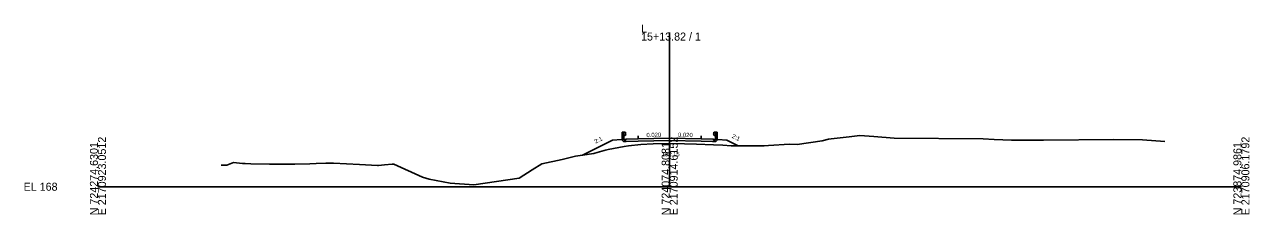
# Model space of a CAD drawing. Extents: x -26 to 2803, y -10 to 9553.
# Drawn here: x -25.7 to 402.8, y 6490.3 to 6556.7 of the extents above; entities that cross this region are included whole.
import ezdxf

# ---------------------------------------------------------------- set-up
doc = ezdxf.new("R2010")
doc.units = 0
for name, color, linetype in [('Exist Cross Section Cell', 7, 'Continuous'), ('Exist XS Center Line Elevation Label', 7, 'Continuous'), ('Exist XS Ground Line', 7, 'Continuous'), ('Prop XS Dump Level', 7, 'Continuous'), ('Prop XS Earthwork Shape', 7, 'Continuous'), ('Prop XS EOT Tick Mark', 7, 'Continuous'), ('Prop XS Finish Grade', 7, 'Continuous'), ('Prop XS Finish Grade Earthwork', 7, 'Continuous'), ('Prop XS Finish Grade Paved Shoulder', 7, 'Continuous'), ('Prop XS Finish Grade Pavement', 7, 'Continuous'), ('Prop XS Guardrail', 7, 'Continuous'), ('Prop XS Pvmt Edge Slope', 7, 'Continuous'), ('Prop XS SE Text', 7, 'Continuous'), ('Prop XS Side Slope Text', 7, 'Continuous'), ('Prop XS Subgrade Earthwork', 7, 'Continuous')]:
    doc.layers.add(name, color=color, linetype=linetype)

msp = doc.modelspace()

# ---------------------------------------------------------------- linework, layer by layer
at = {"layer": 'Exist Cross Section Cell'}
for p, q in [((200, 6500), (200, 6553.89)), ((0, 6500), (200, 6500)), ((200, 6500), (400, 6500))]:
    msp.add_line(p, q, dxfattribs=at)
at = {"layer": 'Exist XS Ground Line'}
msp.add_lwpolyline([(43.07, 6507.56), (45.03, 6507.5), (47.38, 6508.45), (50.61, 6508.11), (51.5, 6508.08), (53.51, 6508.04), (60.02, 6507.91), (61.85, 6507.9), (66.19, 6507.89), (68.85, 6507.89), (74.18, 6508.05), (76.36, 6508.11), (79.77, 6508.28), (82.39, 6508.2), (91.49, 6507.8), (97.75, 6507.46), (98.09, 6507.46), (100.29, 6507.71), (102.96, 6507.89), (103.52, 6507.94), (113.58, 6503.39), (115.83, 6502.7), (123.27, 6501.22), (131.48, 6500.69), (147.3, 6502.96), (151.91, 6505.9), (155.32, 6508.06), (162.41, 6509.53), (167.1, 6510.74), (173.51, 6511.58), (173.81, 6511.78), (177.09, 6512.67), (177.54, 6512.82), (178.45, 6513.01), (184.13, 6514.11), (185.65, 6514.27), (189.86, 6514.79), (194.25, 6514.97), (199.83, 6515.16), (205.22, 6514.98), (209.44, 6514.86), (215.28, 6514.67), (218.61, 6514.58), (221.57, 6514.34), (222.7, 6514.29), (225.56, 6514.29), (229.95, 6514.26), (233.04, 6514.31), (234.55, 6514.43), (241.9, 6514.83), (244.66, 6514.82), (253.38, 6516), (255.54, 6516.57), (256.48, 6516.69), (262.79, 6517.47), (266.53, 6517.96), (271.41, 6517.53), (278.54, 6516.97), (309.65, 6516.71), (313.52, 6516.54), (319.61, 6516.26), (320.03, 6516.26), (330.82, 6516.33), (355.34, 6516.51), (365.4, 6516.4), (373.27, 6515.84)], dxfattribs=at)
at = {"layer": 'Prop XS Dump Level'}
for p, q in [((189, 6516.76), (200, 6516.98)), ((200, 6516.98), (211, 6516.76))]:
    msp.add_line(p, q, dxfattribs=at)
at = {"layer": 'Prop XS Earthwork Shape'}
msp.add_lwpolyline([(211, 6515.92), (200, 6516.14), (189, 6515.92), (184.75, 6515.84), (183.9, 6515.82), (183.18, 6516.55), (180, 6516.29), (169.53, 6511.06), (173.51, 6511.58), (173.81, 6511.78), (177.09, 6512.67), (177.54, 6512.82), (178.45, 6513.01), (184.13, 6514.11), (185.65, 6514.27), (189.86, 6514.79), (194.25, 6514.97), (199.83, 6515.16), (205.22, 6514.98), (209.44, 6514.86), (215.28, 6514.67), (218.61, 6514.58), (221.57, 6514.34), (222.7, 6514.29), (224.01, 6514.29), (220, 6516.29), (216.82, 6516.55), (216.1, 6515.82), (215, 6515.84)], close=True, dxfattribs=at)
at = {"layer": 'Prop XS EOT Tick Mark'}
for p, q in [((189, 6516.76), (189, 6517.76)), ((211, 6516.76), (211, 6517.76))]:
    msp.add_line(p, q, dxfattribs=at)
at = {"layer": 'Prop XS Finish Grade'}
for p, q in [((184.75, 6516.67), (183.18, 6516.55)), ((215.25, 6516.67), (216.82, 6516.55))]:
    msp.add_line(p, q, dxfattribs=at)
at = {"layer": 'Prop XS Finish Grade Earthwork'}
for p, q in [((180, 6516.29), (169.53, 6511.06)), ((183.18, 6516.55), (180, 6516.29)), ((216.82, 6516.55), (220, 6516.29)), ((220, 6516.29), (224.01, 6514.29))]:
    msp.add_line(p, q, dxfattribs=at)
at = {"layer": 'Prop XS Finish Grade Paved Shoulder'}
for p, q in [((189, 6516.76), (184.75, 6516.67)), ((211, 6516.76), (215.25, 6516.67))]:
    msp.add_line(p, q, dxfattribs=at)
at = {"layer": 'Prop XS Finish Grade Pavement'}
for p, q in [((189, 6516.76), (200, 6516.98)), ((200, 6516.98), (211, 6516.76))]:
    msp.add_line(p, q, dxfattribs=at)
at = {"layer": 'Prop XS Guardrail'}
for p, q in [((183.43, 6519.06), (183.93, 6519.06)), ((183.43, 6516.56), (183.43, 6519.06)), ((183.93, 6519.06), (184.43, 6519.06)), ((183.93, 6519.06), (183.93, 6516.56)), ((184.43, 6519.06), (184.72, 6518.86)), ((184.72, 6518.74), (184.43, 6518.54)), ((184.43, 6518.54), (184.43, 6518.45)), ((184.43, 6518.45), (184.72, 6518.25)), ((184.72, 6518.13), (184.43, 6517.93)), ((184.72, 6518.86), (184.75, 6518.8)), ((184.75, 6518.8), (184.72, 6518.74)), ((184.72, 6518.25), (184.75, 6518.19)), ((184.75, 6518.19), (184.72, 6518.13)), ((215.29, 6518.87), (215.26, 6518.81)), ((215.26, 6518.81), (215.29, 6518.75)), ((215.29, 6518.26), (215.26, 6518.2)), ((215.26, 6518.2), (215.29, 6518.14)), ((215.58, 6519.07), (215.29, 6518.87)), ((215.29, 6518.75), (215.58, 6518.55)), ((215.58, 6518.46), (215.29, 6518.26)), ((215.29, 6518.14), (215.58, 6517.94)), ((216.08, 6519.07), (215.58, 6519.07)), ((215.58, 6518.55), (215.58, 6518.46)), ((216.58, 6519.07), (216.08, 6519.07)), ((216.08, 6519.07), (216.08, 6516.57)), ((216.58, 6516.57), (216.58, 6519.07)), ((184.43, 6517.93), (183.93, 6517.93)), ((215.58, 6517.94), (216.08, 6517.94))]:
    msp.add_line(p, q, dxfattribs=at)
at = {"layer": 'Prop XS Pvmt Edge Slope'}
for p, q in [((184.75, 6516.67), (183.9, 6515.82)), ((215.25, 6516.67), (216.1, 6515.82))]:
    msp.add_line(p, q, dxfattribs=at)
at = {"layer": 'Prop XS Subgrade Earthwork'}
for p, q in [((183.9, 6515.82), (183.18, 6516.55)), ((184.75, 6515.84), (183.9, 6515.82)), ((189, 6515.92), (184.75, 6515.84)), ((200, 6516.14), (189, 6515.92)), ((211, 6515.92), (200, 6516.14)), ((211, 6515.92), (215, 6515.84)), ((215, 6515.84), (216.1, 6515.82)), ((216.1, 6515.82), (216.82, 6516.55))]:
    msp.add_line(p, q, dxfattribs=at)

# ---------------------------------------------------------------- texts
at = {"layer": 'Exist Cross Section Cell'}
for s, p in [('L', (190, 6553.89)), ('15+13.82 / 1', (190, 6551.09)), ('EL 168', (-26, 6498.6))]:
    msp.add_text(s, height=2.8, dxfattribs=at).set_placement(p)
for s, p in [('N 724274.6301', (0, 6490)), ('E 2170923.0512', (2.8, 6490)), ('N 724074.8081', (200, 6490)), ('E 2170914.6152', (202.8, 6490)), ('N 723874.9861', (400, 6490)), ('E 2170906.1792', (402.8, 6490))]:
    msp.add_text(s, height=2.8, rotation=90, dxfattribs=at).set_placement(p)
at = {"layer": 'Exist XS Center Line Elevation Label'}
msp.add_text('183.15', height=1.5, dxfattribs=at).set_placement((197.16, 6510.65))
at = {"layer": 'Prop XS SE Text'}
for rotation, p in [(1.1458, (191.88, 6517.32)), (358.8542, (202.88, 6517.42))]:
    msp.add_text('0.020', height=1.5, rotation=rotation, dxfattribs=at).set_placement(p)
at = {"layer": 'Prop XS Side Slope Text'}
for rotation, p in [(333.4349, (221.6, 6517.17)), (26.5651, (174.11, 6515.03))]:
    msp.add_text('2:1', height=1.5, rotation=rotation, dxfattribs=at).set_placement(p)

doc.saveas('drawing.dxf')
